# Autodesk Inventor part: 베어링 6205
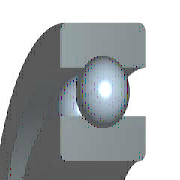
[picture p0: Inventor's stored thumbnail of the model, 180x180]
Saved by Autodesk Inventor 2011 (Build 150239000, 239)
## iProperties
IsCustomPart: 1
Company: 한국ATC센터
Created: 2014-11
Part Number: 베어링 6205
Material: 강, 연강
Description: 깊은 그루브 볼 베어링
Document SubType Name: Modeling
Standard: KS B 2023
Designer: KYOUNG IL JANG
Standards Organization: KS
Language: ko-KR
Size Designation: 6205 - 25 x 52 x 15
Categories: <MemberInstance><Categories><Category DisplayName="샤프트 부품" InternalName="7f7aeb1f-a693-4053-b835-cee3144e0d98" Mnemonic="SHFT"><Category DisplayName="베어링" Inter
Density: 7.86 g/cm^3
Mass: 129.543 g
Surface Area: 107.326 cm^2
Volume: 16.4813 cm^3
Author: KYOUNG IL JANG
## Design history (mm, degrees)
revolve "본체" stored, may be unused: angle "d6" = 90 deg
revolve "볼" stored, may be unused: angle "d7" = 90 deg
pattern_circular "IDS_ARRAYBALL[SIMPL:T]" dims angle "d3" = 360 deg
body "Solid1"
sketch "스케치" dims "d0" = 7.02 (= -0.26 x WD + 0.26 x BD)
  geometry: L1 (3.99, 19.25)-(11.01, 19.25); L2 (7.5, 19.25)-(7.5, 15.74); L3 (7.5, 19.25)-(7.5, 22.76); L4 (4.892, 16.901)-(0, 16.901); L5 (0, 12.5)-(15, 12.5); L6 (4.892, 21.599)-(0, 21.599); L7 (0, 26)-(15, 26); L8 (15, 12.5)-(15, 16.901); L9 (10.108, 16.901)-(15, 16.901); L10 (10.108, 21.599)-(15, 21.599); L11 (15, 26)-(15, 21.599); L12 (-1.4, 0)-(8.4, 0) reference; L13 (0, -0.3)-(0, 5.3) reference
  constraints: 22 end point, 4 point on line, 2 collinear, 2 perpendicular, 2 symmetric about line, 1 midpoint, 1 parallel, 14 other
  dimensions: "d9" = 25 diameter of L5 L12 (= WD); "d11" = 52 diameter of L7 L12 (= BD); "d12" = 15 distance between parallel lines of L8 L13 (= KB); "d13" = 33.802 diameter of L9 L12 (= 0.326 x BD + 0.674 x WD)
fillet "모깎기1" dims "d1" = 1 (= KRS)
other parameters: "WD" = 25 [user parameter; used in 5 equation terms], "BD" = 52 [user parameter; used in 5 equation terms], "KB" = 15 [user parameter; used in 1 equation term], "KRS" = 1 [user parameter; used in 1 equation term], "d4" = 0, "d5" = 0, "d8" = 0, "d14" = 0, "d15" = 0, "BBA" = 0 [user parameter], "BC0" = 7800000 [user parameter], "BC" = 1.4e+07 [user parameter], "BR" = 26 (= 0.5 x BD) [user parameter], "WR" = 12.5 (= 0.5 x WD) [user parameter]
